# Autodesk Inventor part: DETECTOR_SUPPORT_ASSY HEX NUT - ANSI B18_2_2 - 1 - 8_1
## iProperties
Shininess: 64.0
Length Units: 11272
Angle Units: 11279
Time Units: 11290
Mass Units: 11286
Length Display Precision: 3
Angle Display Precision: 2
Compacted: True
Part Number: DETECTOR_SUPPORT_ASSY HEX NUT - ANSI B18_2_2 - 1 - 8_1
Document SubType Name: Modeling
Created: 2004-08
Designer: John Blackburn
Material: MILD_STEEL
Manufacturer: Standard
Standards Organization: Custom
Density: 0.0
Volumn: 0.0
Area: 0.0
PropertySet Name: Model Information
Control State: 0
Master: False
Checked Out: False
Author: John Blackburn
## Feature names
1. Base1
